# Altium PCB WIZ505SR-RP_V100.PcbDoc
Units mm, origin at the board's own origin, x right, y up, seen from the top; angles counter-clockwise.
Board outline 62 x 40 mm, 4 copper layers (Top Layer, Internal Plane 1, Internal Plane 2, Bottom Layer), stack 0.844 mm thick; 87 components, 75 nets, 318 pads, 242 vias.
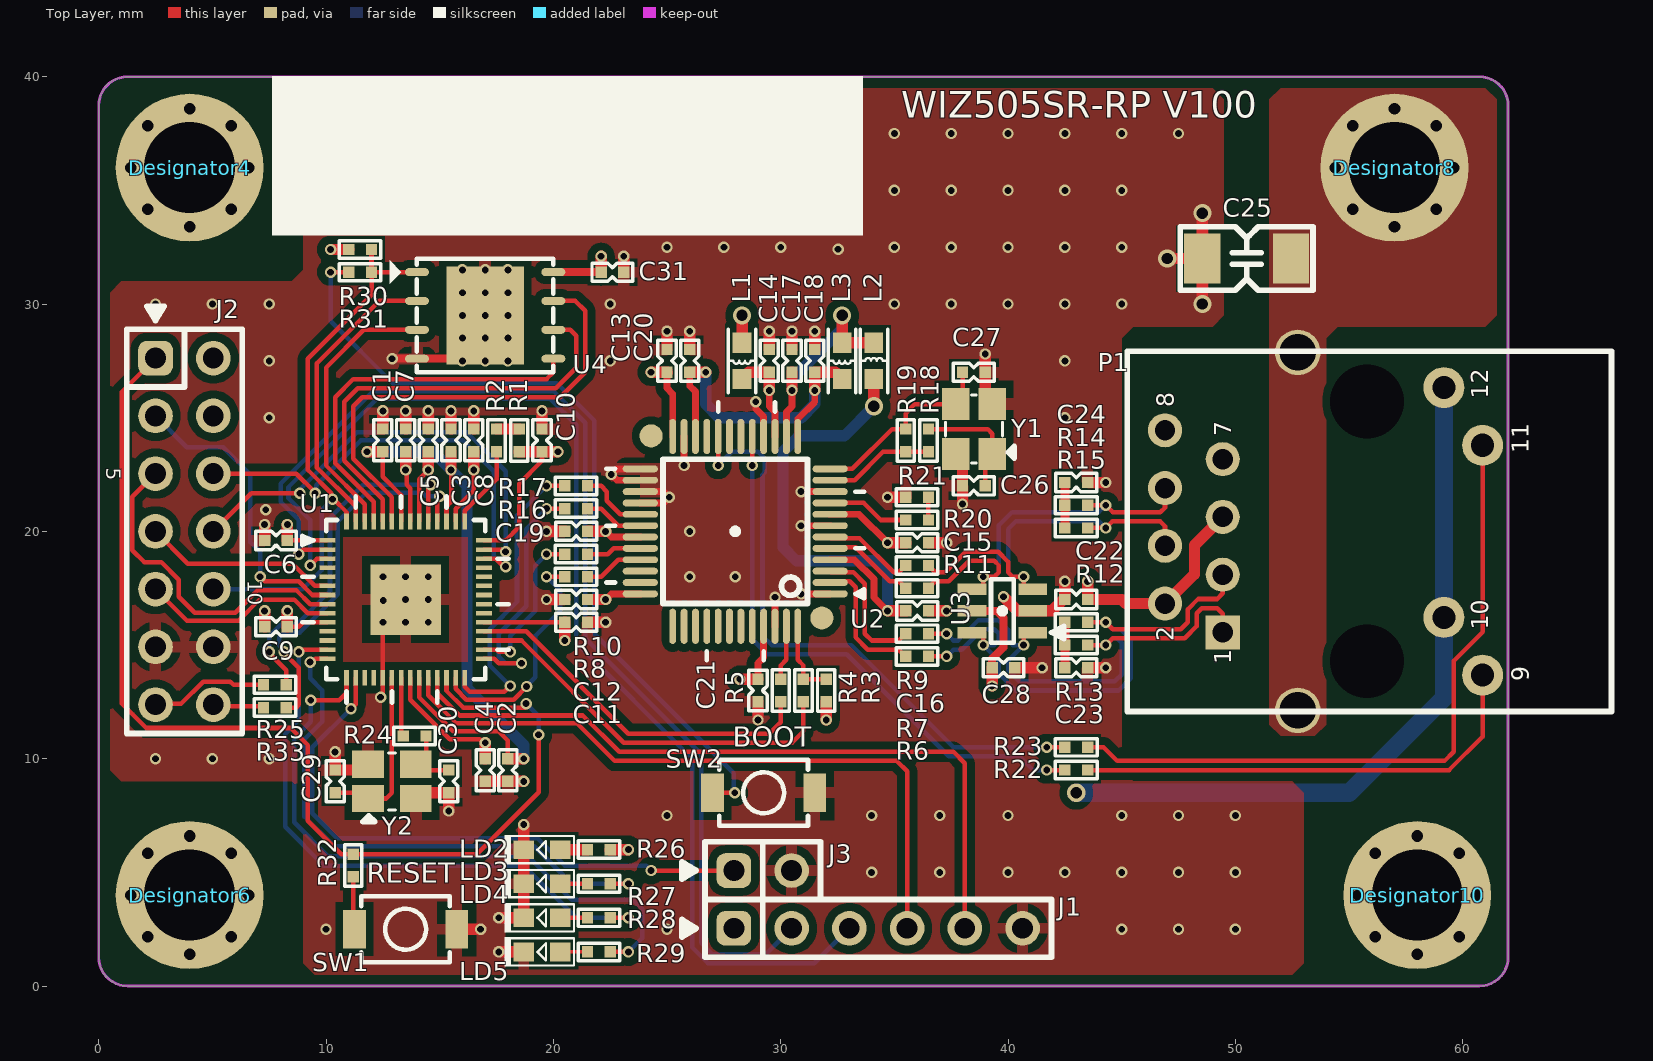
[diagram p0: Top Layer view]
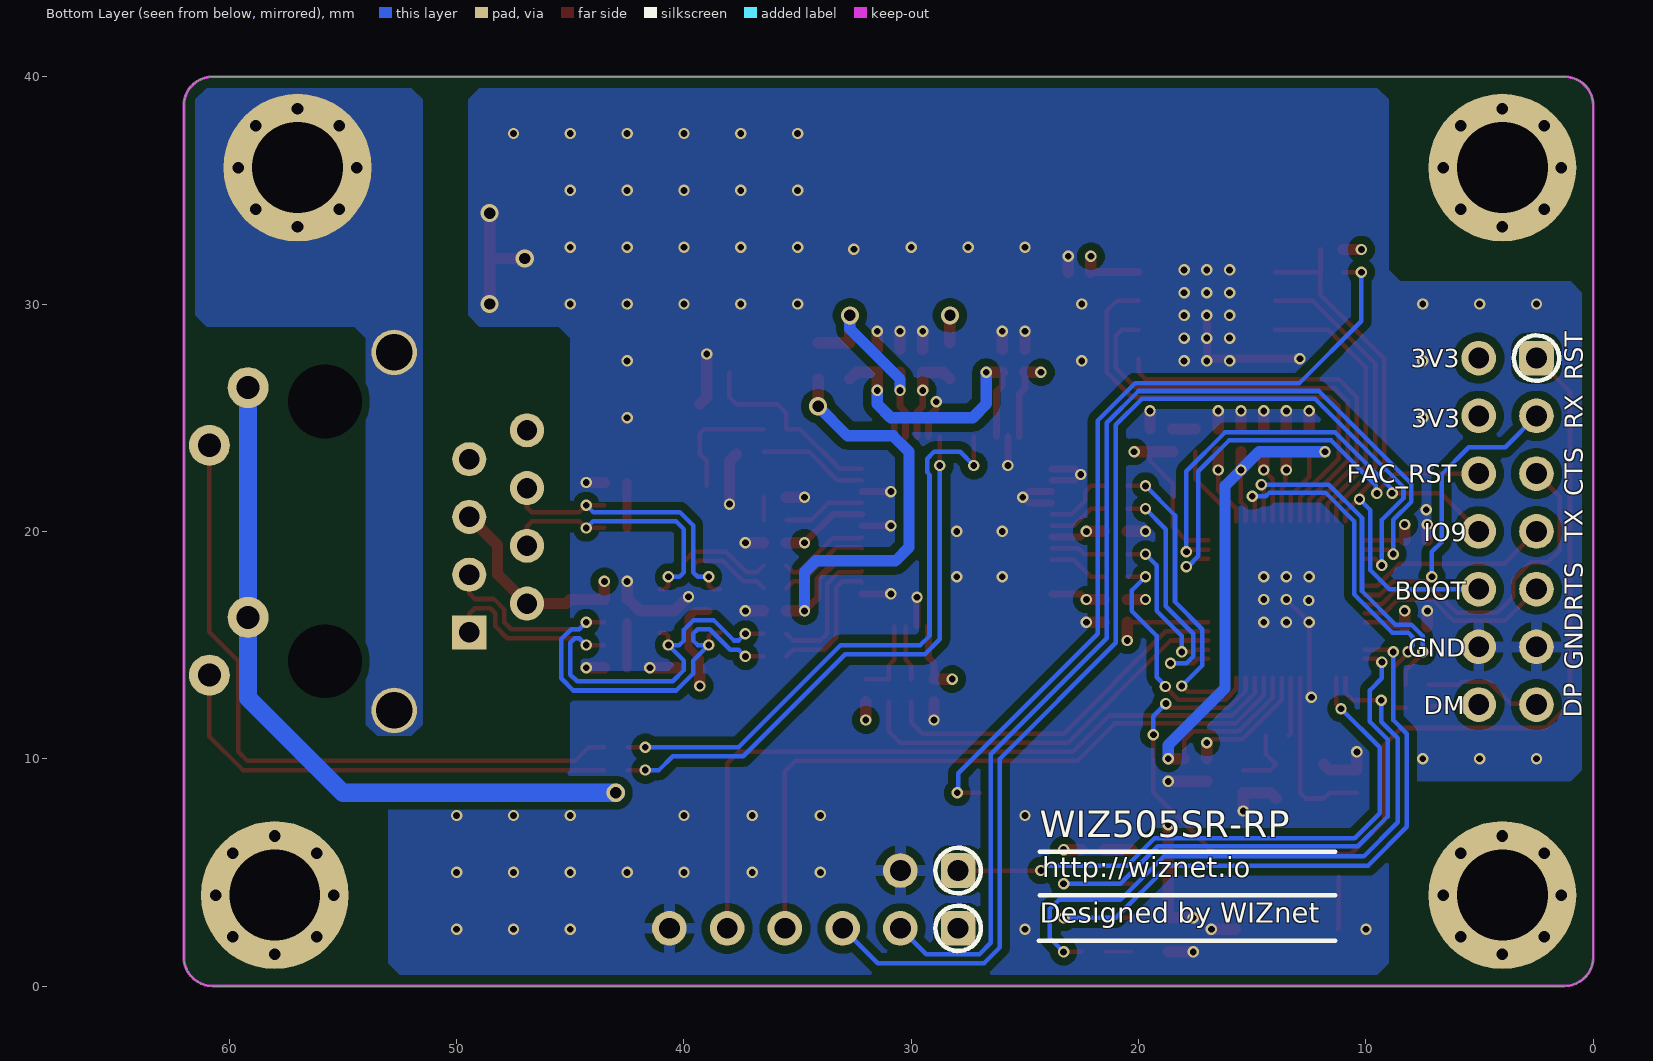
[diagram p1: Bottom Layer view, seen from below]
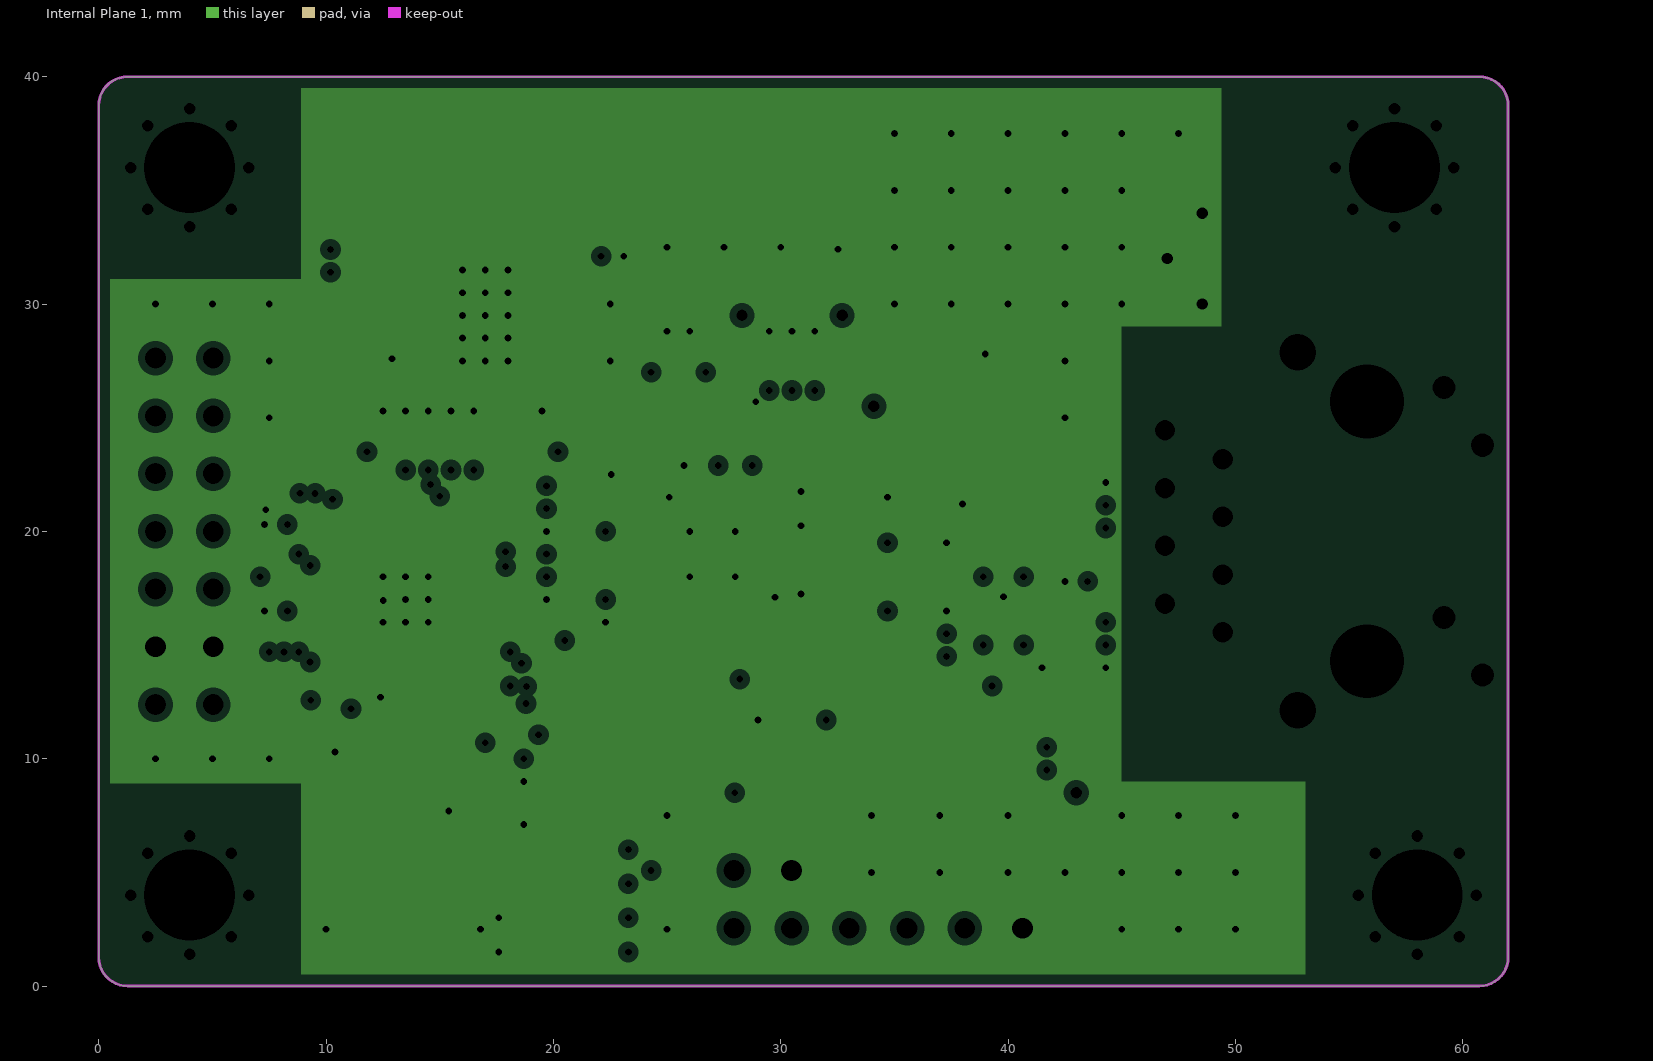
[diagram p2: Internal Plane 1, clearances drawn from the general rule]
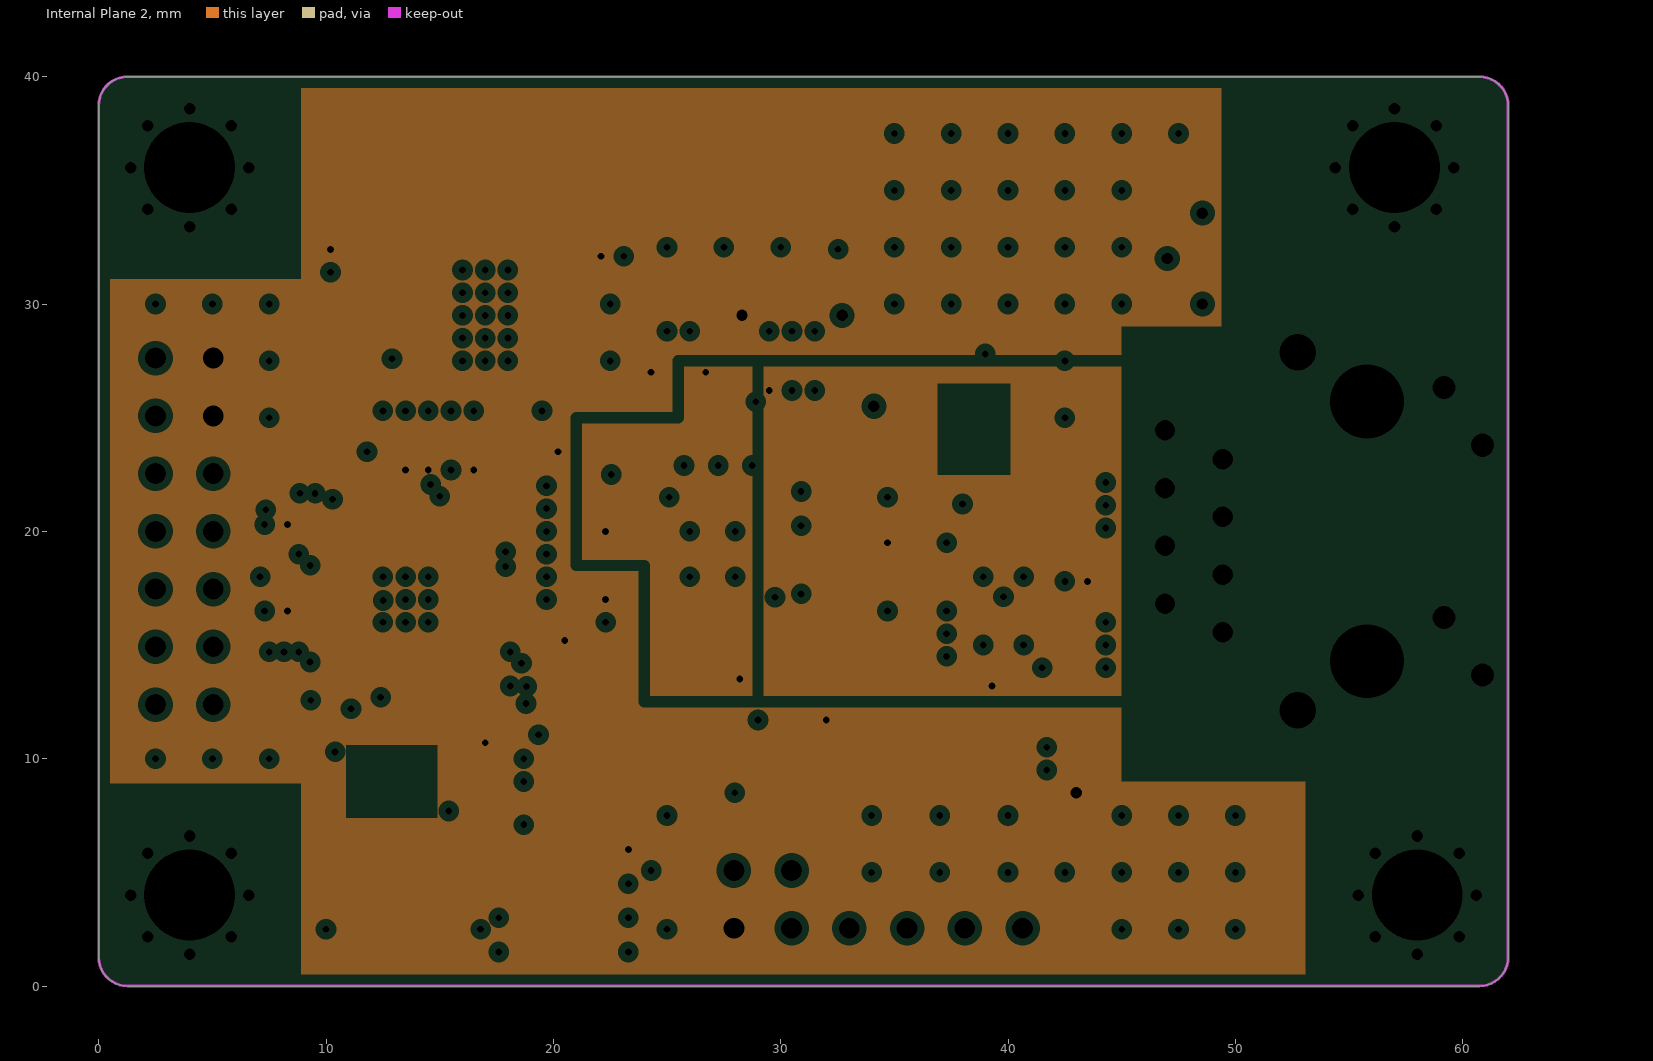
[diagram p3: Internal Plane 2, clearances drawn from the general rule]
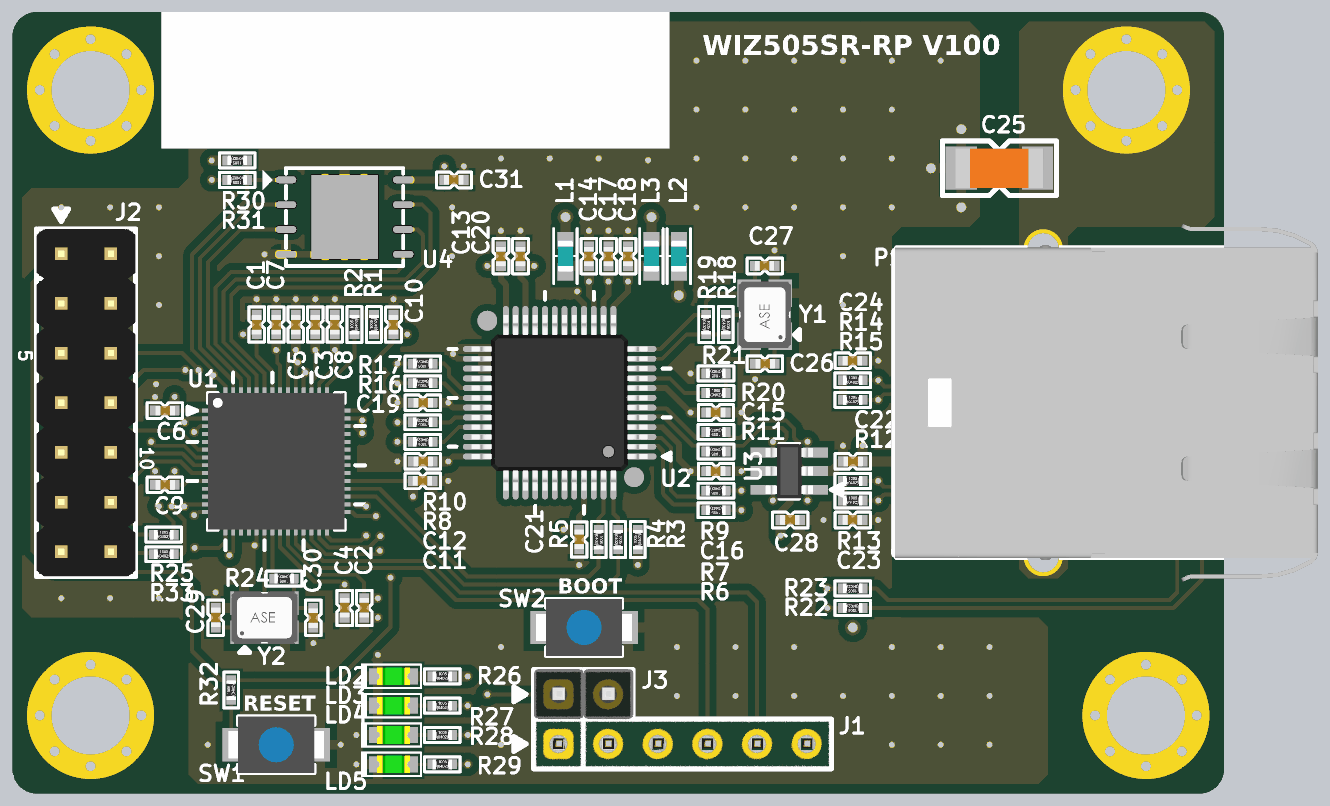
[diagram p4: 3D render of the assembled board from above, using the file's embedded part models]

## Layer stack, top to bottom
Top Solder: solder mask 0.0102, Solder Resist, Dk 3.5
Top Layer: signal copper 0.0356
Dielectric1: core 0.32, FR-4, Dk 4.8
Internal Plane 1: plane copper 0.0356, net GND
Dielectric 6: prepreg 0.127, Dk 4.2
Internal Plane 2: plane copper 0.036, net (Multiple Nets)
Dielectric5: core 0.254, FR-4, Dk 4.2
Bottom Layer: signal copper 0.0356
Bottom Solder: solder mask 0.0102, Solder Resist, Dk 3.5

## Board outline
0,1.27 0,38.73 cw(c1.27,38.73) 1.27,40 60.73,40 cw(c60.73,38.73) 62,38.73 62,1.27 cw(c60.73,1.27) 60.73,0 1.27,0 cw(c1.27,1.27)

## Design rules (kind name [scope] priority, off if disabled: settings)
Clearance [All] p1: gap=0.15 ignorepadtopadclearanceinfootprint=FALSE except(0: Arc-Hole Track-Hole SMDPad-Hole THPad-Hole Via-Hole Fill-Hole Region-Hole Text-Hole; 0.35: Arc-Poly Track-Poly SMDPad-Poly THPad-Poly Via-Poly Fill-Poly Poly-Poly Poly-Region Poly-Text Poly-Hole)
DiffPairsRouting [All] p1: maxlimit=0.2 minlimit=0.2 mostfreqgap=0.2 toplayer_minwidth=0.2 toplayer_maxwidth=0.2 toplayer_prefwidth=0.2 bottomlayer_minwidth=0.2 bottomlayer_maxwidth=0.2 bottomlayer_prefwidth=0.2 maxuncoupledlength=15.24
HoleSize [All] p1: absolutevalues=TRUE maxlimit=4.064 minlimit=0.025 maxpercent=80.000 minpercent=20.000
PlaneClearance [All] p1: clearance=0.305
PlaneConnect [All] p1: planeconnectstyle=Direct reliefexpansion=0.508 reliefentries=4 reliefconductorwidth=0.254 reliefairgap=0.254
PolygonConnect PolygonConnect_1 [InNet('CHGND')] p1: connectstyle=Direct reliefconductorwidth=0.254 reliefentries=4 polygonreliefangle="90 Angle" airgapwidth=0.254
PolygonConnect [All] p2: thpad.connectstyle=Relief thpad.reliefconductorwidth=0.5 thpad.reliefentries=4 thpad.polygonreliefangle="90 Angle" thpad.airgapwidth=0.35 smdpad.connectstyle=Relief smdpad.reliefconductorwidth=0.5 smdpad.reliefentries=4 smdpad.polygonreliefangle="90 Angle" smdpad.airgapwidth=0.35 via.connectstyle=Direct via.reliefconductorwidth=0.254 via.reliefentries=4 via.polygonreliefangle="90 Angle" via.airgapwidth=0.254
RoutingVias [All] p1: holewidth=0.3 width=0.5 viastyle="Through Hole" minholewidth=0.3 minwidth=0.5 maxholewidth=0.6 maxwidth=1
SolderMaskExpansion [All] p1: expansion=0 istentingtop=FALSE
Width [All] p1: maxlimit=2.54 minlimit=0.102 preferedwidth=0.152
26 further rules are at their usual default settings.

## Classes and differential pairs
component class 1.WIZ750JR_W7500: LD2
differential pair TX: +TX_P -TX_N
differential pair RX: +RX_P -RX_N

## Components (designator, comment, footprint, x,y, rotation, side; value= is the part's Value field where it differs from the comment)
C1 "1uF" CAP-0402 12.5,24 r270 top
C2 "0.1uF" CAP-0402 18,9.5 r90 top
C3 "0.1uF" CAP-0402 15.5,24 r270 top
C4 "1uF" CAP-0402 17,9.5 r90 top
C5 "0.1uF" CAP-0402 14.5,24 r270 top
C6 "0.1uF" CAP-0402 7.8,19.6 r0 top
C7 "0.1uF" CAP-0402 13.5,24 r270 top
C8 "0.1uF" CAP-0402 16.5,24 r270 top
C9 "0.1uF" CAP-0402 7.8,15.8 r0 top
C10 "0.1uF" CAP-0402 19.5,24 r270 top
C11 "0.1uF" CAP-0402 21,16 r180 top
C12 "0.1uF" CAP-0402 21,17 r0 top
C13 "0.1uF" CAP-0402 25,27.5 r270 top
C14 "0.1uF" CAP-0402 29.5,27.5 r270 top
C15 "0.1uF" CAP-0402 36,19.5 r180 top
C16 "0.1uF" CAP-0402 36,16.5 r180 top
C17 "1uF" CAP-0402 30.5,27.5 r270 top
C18 "0.1uF" CAP-0402 31.5,27.5 r270 top
C19 "0.1uF" CAP-0402 21,20 r0 top
C20 "0.1uF" CAP-0402 26,27.5 r270 top
C21 "0.1uF" CAP-0402 29,13 r90 top
C22 "0.1uF" CAP-0402 43,17 r0 top
C23 "0.1uF" CAP-0402 43,14 r180 top
C24 "0.1uF" CAP-0402 43,22.15 r180 top
C25 "1nF/2kV" CAP-1808 50.5,32 r0 top
C26 "18pF" CAP-0402 38.5,22 r0 top
C27 "18pF" CAP-0402 38.5,27 r180 top
C28 "0.1uF" CAP-0402 39.8,14 r180 top
C29 "15pF" CAP-0402 10.4,9 r90 top
C30 "15pF" CAP-0402 15.4,9 r270 top
C31 "0.1uF" CAP-0402 22.6,31.4 r180 top
Designator4 "Comment" HOLE-4/6.5 4,36 r0 top
Designator6 "Comment" HOLE-4/6.5 4,4 r0 top
Designator8 "Comment" HOLE-4/6.5 57,36 r0 top
Designator10 "Comment" HOLE-4/6.5 58,4 r0 top
J1 "2.54mm 1x6 Pin Header DIP" IDC-1X6 27.94,2.54 r0 top
J2 "2.54mm 2x7 Pin Header DIP" IDC-2X7 2.5,27.62 r270 top
J3 "2.54mm 1x2 Pin Header DIP" IDC-1X2 27.94,5.08 r0 top
L1 "HH-1M1608-121JT" IND-0603#1 28.3,27.5 r270 top
L2 "HH-1M1608-121JT" IND-0603#1 34.1,27.5 r90 top
L3 "HH-1M1608-121JT" IND-0603#2 32.7,27.5 r270 top
LD2 "Red" LED-0603-green 19.5,6 r180 top
LD3 "Green" LED-0603-green 19.5,4.5 r180 top
LD4 "Green" LED-0603-green 19.5,3 r180 top
LD5 "Green" LED-0603-green 19.5,1.5 r180 top
P1 "J1B1211CCD" RJ45-J1B1211CCD 63.595,20 r90 top locked
R1 "200R" RES-0402#1 18.5,24 r90 top
R2 "1R" RES-0402#1 17.5,24 r90 top
R3 "4.7K" RES-0402#1 32,13 r90 top
R4 "0R" RES-0402#1 31,13 r270 top
R5 "0R" RES-0402#1 30,13 r270 top
R6 "3.3R" RES-0402#1 36,14.5 r180 top
R7 "3.3R" RES-0402#1 36,15.5 r180 top
R8 "0R" RES-0402#1 21,18 r180 top
R9 "3.3R" RES-0402#1 36,17.5 r180 top
R10 "0R" RES-0402#1 21,19 r180 top
R11 "3.3R" RES-0402#1 36,18.5 r180 top
R12 "49.9R" RES-0402#1 43,16 r0 top
R13 "49.9R" RES-0402#1 43,15 r0 top
R14 "49.9R" RES-0402#1 43,21.15 r0 top
R15 "49.9R" RES-0402#1 43,20.15 r0 top
R16 "0R" RES-0402#1 21,21 r180 top
R17 "0R" RES-0402#1 21,22 r180 top
R18 "0R" RES-0402#1 36.5,24 r270 top
R19 "1M" RES-0402#1 35.5,24 r270 top
R20 "12K/1%" RES-0402#1 36,20.5 r0 top
R21 "300R" RES-0402#1 36,21.5 r180 top
R22 "470R" RES-0402#1 43,9.5 r180 top
R23 "470R" RES-0402#1 43,10.5 r180 top
R24 "1K" RES-0402#1 13.9,11 r180 top
R25 "0R" RES-0402#1 7.75,13.25 r0 top
R26 "470R" RES-0402#1 22,6 r0 top
R27 "470R" RES-0402#1 22,4.5 r0 top
R28 "470R" RES-0402#1 22,3 r0 top
R29 "470R" RES-0402#1 22,1.5 r0 top
R30 "NC" RES-0402#1 11.5,32.4 r180 top
R31 "1K" RES-0402#1 11.5,31.4 r180 top
R32 "1K" RES-0402#1 11.2,5.3 r90 top
R33 "0R" RES-0402#2 7.75,12.25 r0 top
SW1 "1185SA(2.0)" ST-1185S 13.5,2.5 r0 top
SW2 "1185SA(2.0)" ST-1185S 29.25,8.5 r0 top
U1 "RP2040" QFN56(0.4/7X7) 13.5,17 r0 top locked
U2 "W5100S" W5100S_LQFP48(0.5/9.0) 28,20 r180 top locked
U3 "TPD4S009DBKR" TPD4S009DBKR-SOT-23-6L 39.75,16.5 r180 top
U4 "W25Q16JVZPIM" WSON8(6X5_1.27) 17,29.5 r0 top
Y1 "25MHz" OSC-82J0626 38.5,24.5 r90 top
Y2 "12MHz" OSC-TZ1067B 12.9,9 r0 top

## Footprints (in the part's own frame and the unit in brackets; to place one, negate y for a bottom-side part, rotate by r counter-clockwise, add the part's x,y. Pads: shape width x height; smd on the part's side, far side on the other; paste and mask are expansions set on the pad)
CAP-0402 [mm] "Ceramic CAP 0402(1005)"
  rect 0.5x0.5 smd: 1(-0.5,0) 2(0.5,0)
  silkscreen extent -0.9,-0.4 0.9,0.4, body extent -0.48,-0.25 0.52,0.25, height 0.6
CAP-1808 [mm] "Ceramic CAP 1808(4520)"
  rect 1.6x2.2 smd: 1(-1.95,0) 2(1.95,0)
  silkscreen extent -2.92,-1.4 2.92,1.4, body extent -2.25,-1.02 2.25,1.01, height 2
HOLE-4/6.5 [mm]
  round 6.5 hole 4: 1(0,0)
IDC-1X2 [mil]
  rrect50% 60x60 hole 36: 1(0,0)
  round 60 hole 36: 2(100,0)
  silkscreen extent -90,-50 150,50, body extent -49,-49 151,51, height 336
IDC-1X6 [mil] "6-Way 2.54 mm Male Header"
  rrect50% 60x60 hole 36: 1(0,0)
  round 60 hole 36: 2(100,0) 3(200,0) 4(300,0) 5(400,0) 6(500,0)
  silkscreen extent -90,-50 550,50, body extent -49,-49 551,51, height 336
IDC-2X7 [mil]
  rrect50% 60x60 hole 36: 1(0,0)
  round 60 hole 36: 2(0,100) 3(100,0) 4(100,100) 5(200,0) 6(200,100) 7(300,0) 8(300,100) 9(400,0) 10(400,100) 11(500,0) 12(500,100) 13(600,0) 14(600,100)
  silkscreen extent -90,-50 650,150, body extent -50,-50 650,150, height 335
IND-0603#1 [mm] "Inductor 0603(1608)"
  rect 0.89x0.82 smd: 1(-0.8,0) 2(0.8,0)
  Top Layer pour cut-out: -0.254,0.508 -0.254,-0.508 0.254,-0.508 0.254,0.508
  silkscreen extent -1.4,-0.6 1.4,0.6, body extent -0.8,-0.4 0.8,0.4, height 0.95
IND-0603#2 [mm] "Inductor 0603(1608)"
  rect 0.89x0.82 smd: 1(-0.8,0) 2(0.8,0)
  silkscreen extent -1.4,-0.6 1.4,0.6, body extent -0.8,-0.4 0.8,0.4, height 0.95
LED-0603-green [mm] "LED-0603-GREEN"
  rect 0.89x0.82 smd: 1(-0.8,0) 2(0.8,0)
  silkscreen extent -1.41,-0.65 1.65,0.65, body extent -0.85,-0.45 0.85,0.45, height 0.9
OSC-82J0626 [mm]
  rect 1.4x1.2 smd: 1(-1.1,-0.8) 2(1.1,-0.8) 3(1.1,0.8) 4(-1.1,0.8)
  silkscreen extent -1.5,-1.78 1.5,1.25, body extent -1.7,-1.35 1.7,1.35, height 1.06
OSC-TZ1067B [mm]
  rect 1.4x1.2 smd: 1(-1.05,-0.75) 2(1.05,-0.75) 3(1.05,0.75) 4(-1.05,0.75)
  silkscreen extent -1.27,-1.78 0.15,1.25, body extent -1.7,-1.35 1.7,1.35, height 1.06
QFN56(0.4/7X7) [mm]
  rect 0.7x0.2 smd: 1(-3.44,2.6) 2(-3.44,2.2) 3(-3.44,1.8) 4(-3.44,1.4) 5(-3.44,1) 6(-3.44,0.6) 7(-3.44,0.2) 8(-3.44,-0.2) 9(-3.44,-0.6) 10(-3.44,-1) 11(-3.44,-1.4) 12(-3.44,-1.8) 13(-3.44,-2.2) 14(-3.44,-2.6) 29(3.44,-2.6) 30(3.44,-2.2) 31(3.44,-1.8) 32(3.44,-1.4) 33(3.44,-1) 34(3.44,-0.6) 35(3.44,-0.2) 36(3.44,0.2) 37(3.44,0.6) 38(3.44,1) 39(3.44,1.4) 40(3.44,1.8) 41(3.44,2.2) 42(3.44,2.6)
  rect 0.2x0.7 smd: 15(-2.6,-3.44) 16(-2.2,-3.44) 17(-1.8,-3.44) 18(-1.4,-3.44) 19(-1,-3.44) 20(-0.6,-3.44) 21(-0.2,-3.44) 22(0.2,-3.44) 23(0.6,-3.44) 24(1,-3.44) 25(1.4,-3.44) 26(1.8,-3.44) 27(2.2,-3.44) 28(2.6,-3.44) 43(2.6,3.44) 44(2.2,3.44) 45(1.8,3.44) 46(1.4,3.44) 47(1,3.44) 48(0.6,3.44) 49(0.2,3.44) 50(-0.2,3.44) 51(-0.6,3.44) 52(-1,3.44) 53(-1.4,3.44) 54(-1.8,3.44) 55(-2.2,3.44) 56(-2.6,3.44)
  rect 3.1x3.1 smd: 57(0,0)
  silkscreen extent -4.54,-4.54 4.54,4.54, body extent -3.5,-3.5 3.5,3.5, height 0.8
RES-0402#1 [mm]
  rect 0.5x0.5 smd: 1(-0.5,0) 2(0.5,0)
  silkscreen extent -0.91,-0.38 0.91,0.38, body extent -0.5,-0.25 0.5,0.25, height 0.35
RES-0402#2 [mm]
  rect 0.5x0.5 smd: 1(-0.5,-0.004) 2(0.5,-0.004)
  silkscreen extent -0.91,-0.38 0.91,0.38, body extent -0.5,-0.25 0.5,0.25, height 0.35
RJ45-J1B1211CCD [mm]
  rect 1.5x1.5 hole 0.9: 1(-4.445,14.15)
  round 1.5 hole 0.9: 2(-3.175,16.69) 3(-1.905,14.15) 4(-0.635,16.69) 5(0.635,14.15) 6(1.905,16.69) 7(3.175,14.15) 8(4.445,16.69)
  round 1.8 hole 1.02: 9(-6.325,2.72) 10(-3.785,4.42) 11(3.785,2.72) 12(6.325,4.42)
  round 2 hole 1.6: S1(-7.875,10.85) S2(7.875,10.85)
  round 1.8 hole 3.25: ""(-5.715,7.8) ""(5.715,7.8)
  silkscreen extent -7.93,-2.95 7.93,18.35, body extent -9.16,-3.2 9.16,18.64, height 15.09
ST-1185S [mm]
  rect 1x1.7 smd: 1(-2.25,0) 2(2.25,0)
  silkscreen extent -1.95,-1.45 1.95,1.45, body extent -2.45,-1.45 2.45,1.45, height 2
TPD4S009DBKR-SOT-23-6L [mm] "4-Channel ESD Solution for High-Speed Differential Interface"
  rect 1.27x0.508 smd: 1(-1.34,0.95) 2(-1.34,0) 3(-1.34,-0.95) 4(1.34,-0.95) 5(1.34,0) 6(1.34,0.95)
  silkscreen extent -2.72,-1.4 0.5,1.4, body extent -1.21,-1.4 1.21,1.4, height 1.09
W5100S_LQFP48(0.5/9.0) [mm]
  round 1.016 smd: 0(-3.81,3.81) 0(3.7,-4.2)
  oval 1.55x0.3 smd: 1(-4.175,2.75) 2(-4.175,2.25) 3(-4.175,1.75) 4(-4.175,1.25) 5(-4.175,0.75) 6(-4.175,0.25) 7(-4.175,-0.25) 8(-4.175,-0.75) 9(-4.175,-1.25) 10(-4.175,-1.75) 11(-4.175,-2.25) 12(-4.175,-2.75) 25(4.175,-2.75) 26(4.175,-2.25) 27(4.175,-1.75) 28(4.175,-1.25) 29(4.175,-0.75) 30(4.175,-0.25) 31(4.175,0.25) 32(4.175,0.75) 33(4.175,1.25) 34(4.175,1.75) 35(4.175,2.25) 36(4.175,2.75)
  oval 0.3x1.55 smd: 13(-2.75,-4.175) 14(-2.25,-4.175) 15(-1.75,-4.175) 16(-1.25,-4.175) 17(-0.75,-4.175) 18(-0.25,-4.175) 19(0.25,-4.175) 20(0.75,-4.175) 21(1.25,-4.175) 22(1.75,-4.175) 23(2.25,-4.175) 24(2.75,-4.175) 37(2.75,4.175) 38(2.25,4.175) 39(1.75,4.175) 40(1.25,4.175) 41(0.75,4.175) 42(0.25,4.175) 43(-0.25,4.175) 44(-0.75,4.175) 45(-1.25,4.175) 46(-1.75,4.175) 47(-2.25,4.175) 48(-2.75,4.175)
  silkscreen extent -5.67,-5.67 5.68,5.68, body extent -4.5,-4.5 4.5,4.5, height 1.5
WSON8(6X5_1.27) [mm]
  oval 1.05x0.35 smd mask+0.05: 1(-3,1.905) 2(-3,0.635) 3(-3,-0.635) 4(-3,-1.905) 5(3,-1.905) 6(3,-0.635) 7(3,0.635) 8(3,1.905)
  rect 3.4x4.3 smd mask+0.05: 9(0,0)
  silkscreen extent -4.2,-2.5 3,2.5, body extent -3,-2.5 3,2.5, height 0.8

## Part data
C1 C2 C3 C4 C5 C6 C7 C8 C9 C10 C11 C12 C13 C14 C15 C16 C17 C18 C19 C20 C21 C22 C23 C24 C26 C27 C28 C29 C30 C31: library part CAP-0402, "Ceramic CAP 0402(1005)"
C25: library part CAP-1808, "Ceramic CAP 1808(4520)"
L1 L2 L3: library part IND-0603, "Inductor 0603(1608)"
LD2 LD3 LD4 LD5: library part LED-0603, "LED-0603"
R1 R2 R3 R4 R5 R6 R7 R8 R9 R10 R11 R12 R13 R14 R15 R16 R17 R18 R19 R20 R21 R22 R23 R24 R25 R26 R27 R28 R29 R30 R31 R32 R33: library part RES-0402, "RES-0402"
SW1 SW2: library part ITS-1107(SMD), "TACT Switch (SMD)"
U1: "Raspverry Pi, Dual ARM Cortex-M0+ @ 133MHz"
U2: "WIZnet Hardwired TCP/IP Chip"
U3: "4-Channel ESD Solution for High-Speed Differential Interface"
U4: "3V 16M-BIT / SERIAL FLASH MEMORY WITH / DUAL/QUAD SPI, QPI & DTR"
Y1: library part OSC-82J0626-25MHz, "X-tal 25MHz,3.2x2.5 SMD, CL=18pF"
Y2: library part OSC-TZ1067B-12MHz, "X-tal 12MHz,3.2x2.5 SMD, CL=20pF"

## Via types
v1: diameter 0.5, hole 0.3, Top Layer to Bottom Layer, tented both sides, 203 vias
v2: diameter 0.762, hole 0.508, Top Layer to Bottom Layer, 32 vias
v3: diameter 0.8, hole 0.5, Top Layer to Bottom Layer, tented both sides, 7 vias

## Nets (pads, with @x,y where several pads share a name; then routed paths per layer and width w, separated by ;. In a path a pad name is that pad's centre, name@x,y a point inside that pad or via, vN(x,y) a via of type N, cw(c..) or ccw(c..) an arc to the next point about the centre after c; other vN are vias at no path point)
1V1: C1.2 C2.2 C3.2 U1.23 U1.45 U1.50 | length 32.3
  Top Layer w0.2: C1.2 12.5,22.4 13.3,21.6 U1.50 ; U1.23 14.1,12.695 15.595,11.2 17.6,11.2 18,10.8 C2.2 ; U1.45 15.3,21.09 15.5,21.29 v1(15.5,22.7)
  Top Layer w0.5: v1(11.8,23.5) C1.2 ; v1(15.5,22.7) C3.2 ; C2.2 v1(18.7,10)
  Bottom Layer w0.5: v1(11.8,23.5) 14.7,23.5 16.2,22 16.2,13.1 18.7,10.6 v1(18.7,10)
1V2A: C16.2 L2.1 U2.4 | length 21.7
  Top Layer w0.3: U2.4 33.25,18.75 34.1,17.9 34.1,17.1 v1(34.7,16.5)
  Top Layer w0.5: v3(34.1,25.5) L2.1 ; v1(34.7,16.5) C16.2
  Bottom Layer w0.5: v3(34.1,25.5) 32.8,24.2 30.8,24.2 30.1,23.5 30.1,19.3 30.7,18.7 34.2,18.7 34.7,18.2 v1(34.7,16.5)
1V2D: C18.2 C19.2 C20.2 C21.2 L3.2 U2.13 U2.22 U2.31 U2.45 | length 21
  Top Layer w0.3: v1(22.3,20) 22.55,19.75 U2.31 ; C20.2 26,26.4 26.25,26.15 U2.22 ; C21.2 29,14.2 29.25,14.45 U2.45 ; U2.13 30.75,24.95 31.5,25.7 v1(31.5,26.2)
  Top Layer w0.5: C19.2 v1(22.3,20) ; C20.2 v1(26.7,27) ; v1(28.2,13.5) C21.2 ; v1(31.5,26.2) C18.2 32.4,27 L3.2
  Bottom Layer w0.5: v1(26.7,27) 26.7,25.6 27.3,25 30.9,25 31.5,25.6 v1(31.5,26.2)
1V2O: C17.2 L2.2 L3.1 U2.14 | length 9.7
  Top Layer w0.3: U2.14 30.25,25.25 30.5,25.5 v1(30.5,26.2)
  Top Layer w0.5: v1(30.5,26.2) C17.2 ; v3(32.7,29.5) L3.1 L2.2
  Bottom Layer w0.5: v1(30.5,26.2) 30.5,26.7 32.7,28.9 v3(32.7,29.5)
3V3: C4.2 C5.2 C6.2 C7.2 C8.2 C9.2 C10.2 C11.2 C12.2 C13.2 C31.2 J1.1 J2.2 J2.4 L1.1 P1.10 P1.12 R1.1 R3.1 R26.2 R30.2 U1.1 U1.10 U1.22 U1.33 U1.42 U1.44 U1.48 U1.49 U2.24 U2.36 U4.8 | length 76.1
  Top Layer w0.2: C9.2 8.8,15.8 9,16 U1.10 ; C6.2 U1.1 ; v1(13.5,22.7) 13.55,22.65 13.55,22.05 13.7,21.9 U1.49 ; U1.22 13.7,12.6 15.45,10.85 16.769,10.85 16.919,10.7 v1(17,10.7) ; U1.48 14.1,22.3 v1(14.5,22.7) ; U1.44 15.7,20.995 16.5,21.795 v1(16.5,22.7) ; U1.33 C11.2 ; U1.42 17.9,19.6 18.5,20.2 18.5,22.1 19.5,23.1 C10.2
  Top Layer w0.3: v1(22.3,17) 22.55,17.25 U2.36 ; C13.2 25,26.3 25.25,26.05 U2.24
  Top Layer w0.35: U4.8 22.095,31.405 C31.2
  Top Layer w0.5: C9.2 v1(8.3,16.5) ; C6.2 v1(8.3,20.3) ; v1(10.2,32.4) R30.2 ; v1(13.5,22.7) C7.2 ; v1(14.5,22.7) C5.2 ; v1(16.5,22.7) C8.2 ; C4.2 v1(17,10.7) ; R1.1 C10.2 v1(20.2,23.5) ; v1(20.5,15.2) C11.2 ; C12.2 v1(22.3,17) ; C31.2 v1(22.1,32.1) ; R26.2 v1(23.3,6) ; v1(32,11.7) R3.1
  Top Layer w0.508: v1(24.3,27) C13.2 ; L1.1 v3(28.3,29.5)
  Bottom Layer w0.8: v3(43,8.5) 55,8.5 59.175,12.675 P1.10 P1.12
3V3A: C14.2 C15.2 C22.2 C28.2 L1.2 P1.2 P1.5 U2.8 U2.15 U3.5 | length 21.5
  Top Layer w0.3: v1(29.5,26.2) 29.5,25.5 29.75,25.25 U2.15 ; U2.8 33.45,20.75 v1(34.7,19.5)
  Top Layer w0.35: U3.5@38.912,16.5 39.5,16.5 39.8,16.2 39.8,14.9 39.3,14.4 C28.2
  Top Layer w0.5: L1.2 28.6,27 C14.2 v1(29.5,26.2) ; v1(34.7,19.5) C15.2 ; v1(39.3,13.2) C28.2 ; v1(43.5,17.8) C22.2 45,17 45.175,16.825 P1.2 48.2,18.12 48.2,19.39 P1.5
ACTn: R23.2 U2.20 | length 26.9
  Top Layer w0.2: v1(27.25,22.9) U2.20 ; v1(41.7,10.5) R23.2
  Bottom Layer w0.2: v1(27.25,22.9) 27.85,23.5 29,23.5 29.3,23.2 29.3,22.6 29.2,22.5 29.2,15.4 29.6,15 33.1,15 37.6,10.5 v1(41.7,10.5)
ADC_VREF: R1.2 R2.2 | length 1
  Top Layer w0.5: R2.2 R1.2
BLINK: R29.2 U1.15 | length 27.9
  Top Layer w0.2: v1(9.325,12.575) 10.575,12.575 10.9,12.9 U1.15 ; R29.2 v1(23.3,1.5)
  Bottom Layer w0.2: v1(9.325,12.575) 9.325,11.625 8.6,10.9 8.6,7.2 10.1,5.7 18.9,5.7 20.8,3.8 23.5,3.8 23.9,3.4 23.9,2.1 v1(23.3,1.5)
BOOTSEL: J2.10 R30.1 R31.1 U1.56 U4.1 | length 24.3
  Top Layer w0.2: U1.56 10.9,20.85 10.34,21.41 v1(10.283,21.41) 10.226,21.467 10.226,21.68 9.205,22.7 9.2,22.7 9.2,27.6 12.005,30.405 R31.1@12.005,31.405 ; R30.1 R31.1 R31.1@12.005,31.405 ; U4.1 R31.1@12.005,31.405
  Bottom Layer w0.2: J2.10 8.967,17.46 9.804,18.296 9.804,20.931 v1(10.283,21.41)
CHGND: C25.2 Designator8.1 P1.S1 P1.S2
  other v2: 57,33.4 55.162,34.162 58.838,34.162 54.4,36 59.6,36 55.162,37.838 58.838,37.838 57,38.6
FACT_RST: J2.6 U1.40 | length 20
  Top Layer w0.2: J2.6 8.692,22.54 9.52,21.712 v1(9.52,21.673) ; U1.40 17.472,18.8 17.822,18.45 v1(17.9,18.45)
  Bottom Layer w0.2: v1(9.52,21.673) 9.568,21.72 9.568,22.034 11.533,24 16.025,24 17.375,22.65 17.375,18.918 17.843,18.45 v1(17.9,18.45)
GND: C1.1 C2.1 C3.1 C4.1 C5.1 C6.1 C7.1 C8.1 C9.1 C10.1 C11.1 C12.1 C13.1 C14.1 C15.1 C16.1 C17.1 C18.1 C19.1 C20.1 C21.1 C22.1 C23.1 C24.1 C25.1 C26.1 C27.1 C28.1 C29.2 C30.2 C31.1 J1.6 J2.11 J2.12 J3.2 LD2.2 LD3.2 LD4.2 LD5.2 R21.2 SW1.2 SW2.2 U1.19 U1.57 U2.1 U2.7 U2.10 U2.16 U2.23 U2.25 U2.26 U2.27 U2.28 U2.46 U3.2 U4.4 U4.9 Y1.2 Y1.4 Y2.2 Y2.4 | length 71.5
  Top Layer w0.2: v1(12.4,12.7) 12.5,12.8 U1.19 v1(12.5,16) v1(13.5,17)
  Top Layer w0.3: U2.28 24.85,21.25 v1(25.1,21.5) 24.85,21.75 U2.27 ; U2.26 22.8,22.25 v1(22.55,22.5) 22.8,22.75 U2.25 ; v1(25.75,22.9) U2.23 ; v1(28.9,25.7) 28.9,25.4 29.25,25.05 U2.16 ; U2.46 v1(29.75,17.1) ; v1(30.9,17.25) U2.1 ; v1(30.9,20.25) U2.7 ; v1(30.9,21.75) U2.10
  Top Layer w0.35: v1(12.905,27.595) U4.4 17,27.595 v1(17,29.5)
  Top Layer w0.5: C9.1 v1(7.3,16.5) ; C6.1 v1(7.3,20.3) ; v1(10.4,10.3) C29.2 11.6,9.5 Y2.4 ; C1.1 v1(12.5,25.3) ; C7.1 v1(13.5,25.3) ; Y2.2 14.2,8.5 C30.2 v1(15.4,7.7) ; C5.1 v1(14.5,25.3) ; C3.1 v1(15.5,25.3) ; SW1.2 v1(16.8,2.5) ; C8.1 v1(16.5,25.3) ; C4.1 C2.1 v1(18.7,9) ; v1(17.6,1.5) LD5.2 ; v1(17.6,3) LD4.2 LD3.2 LD2.2 v1(18.7,7.1) ; C10.1 v1(19.5,25.3) ; v1(19.7,17) C12.1 ; v1(19.7,20) C19.1 ; C11.1 v1(22.3,16) ; C31.1 v1(23.1,32.1) ; C13.1 v1(25,28.8) ; C20.1 v1(26,28.8) ; v1(29,11.7) C21.1 ; C14.1 v1(29.5,28.8) ; C17.1 v1(30.5,28.8) ; C18.1 v1(31.5,28.8) ; v1(34.7,21.5) R21.2 ; C16.1 v1(37.3,16.5) ; C15.1 v1(37.3,19.5) ; Y1.4 38,23.1 C26.1 v1(38,21.2) ; v1(39,27.8) C27.1 39,25.9 Y1.2 ; v1(39.8,17.125) 40.425,16.5 U3.2 41.094,16.504 41.938,16.504 42.434,17 C22.1 v1(42.5,17.8) ; C28.1 v1(41.5,14) ; C23.1 v1(44.3,14) ; C24.1 v1(44.3,22.15) ; v3(47,32) C25.1 ; v3(48.55,30) C25.1 ; v3(48.55,34) C25.1
  other v1: 10,2.5 25,2.5 45,2.5 47.5,2.5 50,2.5 34,5 37,5 40,5 42.5,5 45,5 47.5,5 50,5 25,7.5 34,7.5 37,7.5 40,7.5 45,7.5 47.5,7.5 50,7.5 2.5,10 5,10 7.5,10 13.5,16 14.5,16 12.519,16.96 14.5,17 12.5,18 13.5,18 14.5,18 26,18 28,18 26,20 28,20 7.35,20.95 7.5,25 42.5,25 7.5,27.5 16,27.5 17,27.5 18,27.5 22.5,27.5 42.5,27.5 16,28.5 17,28.5 18,28.5 16,29.5 18,29.5 2.5,30 5,30 7.5,30 22.5,30 35,30 37.5,30 40,30 42.5,30 45,30 16,30.5 17,30.5 18,30.5 16,31.5 17,31.5 18,31.5 32.526,32.407 25,32.5 27.5,32.5 30,32.5 35,32.5 37.5,32.5 40,32.5 42.5,32.5 45,32.5 35,35 37.5,35 40,35 42.5,35 45,35 35,37.5 37.5,37.5 40,37.5 42.5,37.5 45,37.5 47.5,37.5
HW_TRIG: J2.8 U1.41 | length 20
  Top Layer w0.2: J2.8 6.715,21.675 v1(8.85,21.675) ; U1.41 17.719,19.2 17.819,19.1 v1(17.9,19.1)
  Bottom Layer w0.2: v1(8.85,21.675) 8.907,21.732 8.907,21.907 11.35,24.35 16.2,24.35 17.9,22.65 v1(17.9,19.1)
INTn: R5.2 U1.32 | length 16
  Top Layer w0.2: U1.32 18.8,15.6 23.3,11.1 29.5,11.1 30,11.6 R5.2
LINK_STATUS: R28.2 U1.13 | length 26.8
  Top Layer w0.2: v1(8.8,14.7) 8.9,14.8 U1.13 ; R28.2 v1(23.3,3)
  Bottom Layer w0.2: v1(8.8,14.7) 8.8,11.7 8.2,11.1 8.2,7 9.9,5.3 18.7,5.3 21,3 v1(23.3,3)
LINKn: R22.2 U2.17 | length 25.1
  Top Layer w0.2: v1(28.75,22.9) U2.17 ; v1(41.7,9.5) R22.2
  Bottom Layer w0.2: v1(28.75,22.9) 28.75,15.25 29.4,14.6 32.9,14.6 37.4,10.1 40.5,10.1 41.1,9.5 v1(41.7,9.5)
NetC23_2: C23.2 R12.1 R13.1 | length 2
  Top Layer w0.4: C23.2 R13.1 R12.1
NetC24_2: C24.2 R14.1 R15.1 | length 2
  Top Layer w0.4: R15.1 R14.1 C24.2
NetC26_2: C26.2 R18.1 Y1.1 | length 5.3
  Top Layer w0.2: R18.1 39.1,24.5 39.3,24.3 Y1.1 39,23.1 C26.2
NetC27_2: C27.2 R19.1 U2.12 Y1.3 | length 8.6
  Top Layer w0.2: U2.12 33.15,22.75 34.9,24.5 R19.1 35.5,25.2 35.9,25.6 Y1.3 38,25.9 C27.2
NetC30_1: C30.1 R24.1 Y2.3 | length 3
  Top Layer w0.2: R24.1 14.4,10.2 Y2.3 14.2,9.5 C30.1
NetLD2_1: LD2.1 R26.1 | length 1.2
  Top Layer w0.5: LD2.1 R26.1
NetLD3_1: LD3.1 R27.1 | length 1.2
  Top Layer w0.2: LD3.1 R27.1
NetLD4_1: LD4.1 R28.1 | length 1.2
  Top Layer w0.2: LD4.1 R28.1
NetLD5_1: LD5.1 R29.1 | length 1.2
  Top Layer w0.152: LD5.1 R29.1
NetP1_9: P1.9 R22.1 | length 20.7
  Top Layer w0.2: R22.1 59.4,9.5 60.875,10.975 P1.9
NetP1_11: P1.11 R23.1 | length 30.5
  Top Layer w0.2: R23.1 44.2,10.5 44.8,9.9 59.2,9.9 59.6,10.3 59.6,14.3 60.875,15.575 P1.11
NetR2_1: R2.1 U1.43 | length 3.6
  Top Layer w0.2: U1.43 16.1,20.9 17.5,22.3 R2.1
NetR3_2: R3.2 R4.1 U2.48 | length 3.4
  Top Layer w0.2: U2.48 30.75,14.35 31,14.1 R4.1 R3.2
NetR5_1: R5.1 U2.47 | length 2.4
  Top Layer w0.2: R5.1 30,14.1 30.25,14.35 U2.47
NetR6_2: R6.2 U2.2 | length 6
  Top Layer w0.2: U2.2 32.225,17.8 33.034,17.8 33.3,17.534 33.3,15.334 33.834,14.8 35.2,14.8 R6.2
NetR7_2: R7.2 U2.3 | length 6
  Top Layer w0.2: U2.3 32.225,18.2 33.2,18.2 33.7,17.7 33.7,15.5 34,15.2 35.2,15.2 R7.2
NetR8_1: R8.1 U2.33 | length 2.6
  Top Layer w0.2: R8.1 22.1,18 22.85,18.75 U2.33
NetR9_2: R9.2 U2.5 | length 4.1
  Top Layer w0.2: U2.5 32.225,19.3 33.3,19.3 34.8,17.8 35.2,17.8 R9.2
NetR10_1: R10.1 U2.32 | length 2.4
  Top Layer w0.2: R10.1 22.4,19 22.65,19.25 U2.32
NetR11_2: R11.2 U2.6 | length 4.1
  Top Layer w0.2: U2.6 32.225,19.7 33.466,19.7 34.966,18.2 35.2,18.2 R11.2
NetR16_1: R16.1 U2.30 | length 2.6
  Top Layer w0.2: R16.1 22.1,21 22.85,20.25 U2.30
NetR17_1: R17.1 U2.29 | length 3.1
  Top Layer w0.2: R17.1 22.1,22 22.35,21.75 22.35,21.35 22.95,20.75 U2.29
NetR18_2: R18.2 R19.2 U2.11 | length 4.8
  Top Layer w0.2: U2.11 33.25,22.25 34.5,23.5 R19.2 R18.2
NetR20_1: R20.1 U2.9 | length 3.6
  Top Layer w0.2: U2.9 33.65,21.25 34.4,20.5 R20.1
NetR20_2: R20.2 R21.1 | length 1
  Top Layer w0.2: R20.2 R21.1
NetR25_2: R25.2 U1.47 | length 15.9
  Top Layer w0.2: v1(7.5,14.7) 7.5,14.643 8.25,13.893 R25.2 ; U1.47 14.5,21.877 14.6,21.977 v1(14.6,22.058)
  Bottom Layer w0.2: v1(7.5,14.7) 7.5,15.4 8,15.9 8.7,15.9 10.175,17.375 10.175,20.595 11.638,22.058 v1(14.6,22.058)
NetR31_2: R31.2 SW2.1 | length 36.3
  Top Layer w0.2: v1(10.2,31.4) R31.2 ; SW2.1 v1(27.975,8.5)
  Bottom Layer w0.2: v1(10.2,31.4) 10.2,29.25 12.925,26.525 20.15,26.525 21.8,24.875 21.8,15.5 27.94,9.36 27.94,8.535 v1(27.975,8.5)
NetR32_1: R32.1 SW1.1 | length 2.3
  Top Layer w0.2: R32.1 11.2,2.55 SW1.1
NetR33_2: R33.2 U1.46 | length 16.7
  Top Layer w0.2: v1(8.15,14.7) 8.15,14.643 8.8,13.993 8.8,12.363 8.683,12.246 R33.2 ; U1.46 14.9,21.364 15,21.464 v1(15,21.545)
  Bottom Layer w0.2: v1(8.15,14.7) 8.15,14.781 7.945,14.986 7.945,15.35 8.145,15.55 8.845,15.55 10.525,17.23 10.525,20.45 11.783,21.708 14.243,21.708 14.405,21.545 v1(15,21.545)
PREV_BANK: J3.1 U1.16 | length 26.3
  Top Layer w0.2: v1(11.1,12.2) 11.3,12.4 U1.16 ; v1(24.3,5.08) J3.1
  Bottom Layer w0.2: v1(11.1,12.2) 9.4,10.5 9.4,7.6 10.5,6.5 19.3,6.5 20.5,5.3 24.08,5.3 v1(24.3,5.08)
QSPI1_SCLK: U1.52 U4.6 | length 19.3
  Top Layer w0.2: U1.52 12.5,21.405 10.8,23.105 10.8,25.7 11.4,26.3 20.1,26.3 21,27.2 21,28.6 20.735,28.865 U4.6
QSPI1_SD0: U1.53 U4.5 | length 16.8
  Top Layer w0.2: U1.53 12.1,21.3 10.4,23 10.4,25.9 11.2,26.7 19.7,26.7 20,27 U4.5
QSPI1_SD1: U1.55 U4.2 | length 13.2
  Top Layer w0.2: U1.55 11.3,21.1 9.6,22.8 9.6,27.4 12.335,30.135 U4.2
QSPI1_SD2: U1.54 U4.3 | length 12.2
  Top Layer w0.2: U1.54 11.7,21.2 10,22.9 10,27.2 11.665,28.865 U4.3
QSPI1_SD3: U1.51 U4.7 | length 20.9
  Top Layer w0.2: U1.51 12.9,21.5 11.2,23.2 11.2,25.5 11.6,25.9 20.3,25.9 21.4,27 21.4,29.7 20.965,30.135 U4.7
RSTn: R4.2 U1.31 | length 17.4
  Top Layer w0.2: U1.31 18.6,15.2 23.1,10.7 30.5,10.7 31,11.2 R4.2
RUN: J2.1 R32.2 U1.26 | length 48.6
  Top Layer w0.2: J2.1 1.025,26.145 1.025,12.424 1.488,11.961 2.099,11.35 8.45,11.35 9.2,10.6 9.2,7.275 10.675,5.8 R32.2 16.625,5.8 19.35,8.525 v1(19.35,11.05) ; U1.26 15.3,12.98 16.03,12.25 18.775,12.25 18.775,12.4 v1(18.8,12.425)
  Bottom Layer w0.2: v1(18.8,12.425) 19.35,11.875 v1(19.35,11.05)
RX_N: P1.6 R9.1 R14.2 U3.4 | length 18.1
  Top Layer w0.2: R9.1 36.8,17.8 37.4,17.8 38.3,18.7 39.4,18.7 39.6,18.5 39.6,18.2 39.4,18 v1(38.912,18) 38.912,17.604 38.758,17.45 U3.4 ; R14.2 v1(44.3,21.15) 44.615,20.835 46.7,20.835 46.905,21.04 P1.6
  Bottom Layer w0.2: v1(38.912,18) 39.4,18 39.6,18.2 39.6,20.266 40.184,20.85 44,20.85 v1(44.3,21.15)
RX_P: P1.4 R11.1 R15.2 U3.3 | length 18
  Top Layer w0.2: R11.1 36.8,18.2 37.234,18.2 38.134,19.1 39.566,19.1 40,18.666 40,18.2 40.2,18 v1(40.687,18) 40.687,17.604 40.841,17.45 U3.3 ; R15.2 v1(44.3,20.15) 44.585,20.435 46.7,20.435 46.905,20.23 P1.4
  Bottom Layer w0.2: v1(40.687,18) 40.2,18 40,18.2 40,20.1 40.35,20.45 44,20.45 v1(44.3,20.15)
SPI0_CSn: R17.2 U1.28 | length 13.6
  Top Layer w0.2: U1.28 16.1,13.17 16.32,12.95 17.833,12.95 18.083,13.2 v1(18.1,13.2) ; v1(19.7,22) R17.2
  Bottom Layer w0.2: v1(18.1,13.2) 17.2,14.1 17.2,15.7 18.4,16.9 18.4,20.7 v1(19.7,22)
SPI0_RX: R8.2 U1.27 | length 10.5
  Top Layer w0.2: U1.27 15.7,13.075 16.175,12.6 18.25,12.6 v1(18.825,13.175) ; v1(19.7,18) R8.2
  Bottom Layer w0.2: v1(18.825,13.175) 18.825,13.203 19.2,13.578 19.2,15.4 20.3,16.5 20.3,17.4 v1(19.7,18)
SPI0_SCK: R16.2 U1.29 | length 11
  Top Layer w0.2: U1.29 17.4,14.4 17.6,14.2 v1(18.6,14.2) ; v1(19.7,21) R16.2
  Bottom Layer w0.2: v1(18.6,14.2) 17.9,14.2 17.893,14.2 17.6,14.493 17.6,14.5 17.6,15.5 18.8,16.7 18.8,20.1 v1(19.7,21)
SPI0_TX: R10.2 U1.30 | length 7
  Top Layer w0.2: U1.30 17.5,14.8 17.6,14.7 v1(18.1,14.7) ; v1(19.7,19) R10.2
  Bottom Layer w0.2: v1(18.1,14.7) 18.1,15.4 19.2,16.5 19.2,18.5 v1(19.7,19)
SWCLK: J1.4 U1.24 | length 30.1
  Top Layer w0.2: U1.24 14.5,12.79 15.74,11.55 21.05,11.55 22.7,9.9 35.1,9.9 35.56,9.44 J1.4
SWDIO: J1.5 U1.25 | length 32.4
  Top Layer w0.2: U1.25 14.9,12.885 15.885,11.9 21.3,11.9 22.9,10.3 37.6,10.3 38.1,9.8 J1.5
TCP_STATUS: R27.2 U1.14 | length 24.4
  Top Layer w0.2: v1(9.3,14.25) 9.381,14.25 9.531,14.4 U1.14 ; R27.2 v1(23.3,4.5)
  Bottom Layer w0.2: v1(9.3,14.25) 9.3,13.531 9.825,13.006 9.825,11.63 9.05,10.855 9.05,7.455 10.355,6.15 19.155,6.15 20.805,4.5 v1(23.3,4.5)
TX_N: P1.3 R6.1 R12.2 U3.6 | length 24.6
  Top Layer w0.2: R6.1 v1(37.3,14.5) ; U3.6 38.758,15.55 38.912,15.396 v1(38.912,15) ; R12.2 v1(44.3,16) 44.6,15.7 47.6,15.7 47.9,16 47.9,16.566 48.359,17.025 49.2,17.025 49.445,17.27 P1.3
  Bottom Layer w0.2: v1(37.3,14.5) 37.6,14.8 37.966,14.8 38.866,15.7 39.4,15.7 39.6,15.5 39.6,15.2 39.4,15 v1(38.912,15) 39.6,14.312 39.6,13.734 40.334,13 44.866,13 45.4,13.534 45.4,15.266 44.966,15.7 44.6,15.7 v1(44.3,16)
TX_P: P1.1 R7.1 R13.2 U3.1 | length 23.2
  Top Layer w0.2: R7.1 v1(37.3,15.5) ; v1(40.687,15) 40.687,15.396 40.841,15.55 U3.1 ; R13.2 v1(44.3,15) 44.6,15.3 47.766,15.3 48.3,15.834 48.3,16.4 48.525,16.625 49.2,16.625 49.445,16.38 P1.1
  Bottom Layer w0.2: v1(37.3,15.5) 37.6,15.2 37.8,15.2 38.7,16.1 39.566,16.1 40,15.666 40,15.2 40.2,15 v1(40.687,15) 40,14.312 40,13.9 40.5,13.4 44.7,13.4 45,13.7 45,15.1 44.8,15.3 44.6,15.3 v1(44.3,15)
UART0_RX: J1.3 U1.3 | length 52.4
  Top Layer w0.2: v1(9.304,18.504) 9.6,18.8 U1.3
  Bottom Layer w0.2: v1(9.304,18.504) 9.3,18.507 9.3,20.502 8.35,21.452 8.35,21.95 12.225,25.825 19.86,25.825 21,24.685 21,15.1 26.1,10 26.1,1.7 26.8,1 31.48,1 J1.3
UART0_TX: J1.2 U1.2 | length 50.1
  Top Layer w0.2: v1(8.8,19) 9,19.2 U1.2
  Bottom Layer w0.2: v1(8.8,19) 8.8,20.507 8,21.307 8,22.1 12.075,26.175 20.005,26.175 21.4,24.78 21.4,15.3 26.5,10.2 26.5,1.9 27,1.4 29.34,1.4 J1.2
UART1_CTS: J2.5 U1.8 | length 14.6
  Top Layer w0.2: J2.5 1.475,21.515 1.475,19.175 2,18.65 2.75,18.65 3.525,17.875 3.525,17.125 4.225,16.425 6,16.425 6.975,17.4 8.7,17.4 9.3,16.8 U1.8
UART1_RTS: J2.9 U1.9 | length 8.8
  Top Layer w0.2: J2.9 3.885,16.075 6.15,16.075 7.075,17 8.6,17 9.2,16.4 U1.9
UART1_RX: J2.3 U1.7 | length 13.2
  Top Layer w0.2: v1(7.1,18) 7.3,17.8 8.8,17.8 9.4,17.2 U1.7
  Bottom Layer w0.2: J2.3 3.88,23.7 5.475,23.7 6.675,22.5 6.675,19.525 7.1,19.1 v1(7.1,18)
UART1_TX: J2.7 U1.6 | length 8.6
  Top Layer w0.2: J2.7 3.925,18.575 8.525,18.575 9.5,17.6 U1.6
USB_DM: J2.14 R33.1 | length 2.3
  Top Layer w0.2: J2.14 5.107,12.313 7.183,12.313 R33.1
USB_DP: J2.13 R25.1 | length 5.2
  Top Layer w0.2: J2.13 2.54,12.42 3.62,12.42 4.592,13.392 5.789,13.392 5.931,13.25 R25.1
XIN: C29.1 U1.20 Y2.1 | length 7.8
  Top Layer w0.2: C29.1 11.6,8.5 Y2.1 12.65,8.25 12.9,8.5 U1.20
XOUT: R24.2 U1.21 | length 2.6
  Top Layer w0.2: U1.21 13.3,11.1 R24.2
pads on no net: Designator4.1 Designator6.1 Designator10.1 P1. P1.7 P1.8 U1.4 U1.5 U1.11 U1.12 U1.17 U1.18 U1.34 U1.35 U1.36 U1.37 U1.38 U1.39 U2.0 U2.18 U2.19 U2.21 U2.34 U2.35 U2.37 U2.38 U2.39 U2.40 U2.41 U2.42 U2.43 U2.44
copper on no net:
  other v2: 4,1.4 58,1.4 2.162,2.162 5.838,2.162 56.162,2.162 59.838,2.162 1.4,4 6.6,4 55.4,4 60.6,4 2.162,5.838 5.838,5.838 56.162,5.838 59.838,5.838 4,6.6 58,6.6 4,33.4 2.162,34.162 5.838,34.162 1.4,36 6.6,36 2.162,37.838 5.838,37.838 4,38.6

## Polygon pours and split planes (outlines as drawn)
GND on Top Layer "NONET_L02_P-001" (solid, remove dead copper, pour order 26): 45,9.5 45.5,9 52.5,9 53,8.5 53,1 52.5,0.5 9.5,0.5 9,1 9,8.5 8.5,9 1,9 0.5,9.5 0.5,30.5 1,31 8.5,31 9,31.5 9,39 9.5,39.5 49,39.5 49.5,39 49.5,29.5 49,29 45.5,29 45,28.5
CHGND on Top Layer "NONET_L02_P-001" (solid, remove dead copper, pour order 21): 51.5,11.5 52,11 53.5,11 54,11.5 54,28.5 54.5,29 61,29 61.5,29.5 61.5,39 61,39.5 52,39.5 51.5,39
GND on Top Layer "Top Layer-GND" (solid, remove dead copper, pour order 18): 42.545,28.956 42.545,26.797 42.291,26.543 42.037,26.543 33.909,26.543 33.655,26.797 33.655,27.178 33.655,28.956
GND on Bottom Layer "NONET_L02_P-001" (solid, remove dead copper, pour order 27): 45,9.5 45.5,9 52.5,9 53,8.5 53,1 52.5,0.5 9.5,0.5 9,1 9,8.5 8.5,9 1,9 0.5,9.5 0.5,30.5 1,31 8.5,31 9,31.5 9,39 9.5,39.5 49,39.5 49.5,39 49.5,29.5 49,29 45.5,29 45,28.5
CHGND on Bottom Layer "NONET_L02_P-001" (solid, remove dead copper, pour order 22): 51.5,11.5 52,11 53.5,11 54,11.5 54,28.5 54.5,29 61,29 61.5,29.5 61.5,39 61,39.5 52,39.5 51.5,39
3V3 on Internal Plane 2 (split plane): 49.4,29 45,29 45,27.752 25.5,27.752 25.435,27.744 25.374,27.718 25.322,27.678 25.282,27.626 25.256,27.565 25.248,27.5 25.248,25.252 21,25.252 20.935,25.244 20.874,25.218 20.822,25.178 20.782,25.126 20.756,25.065 20.748,25 20.748,18.5 20.756,18.435 20.782,18.374 20.822,18.322 20.874,18.282 20.935,18.256 21,18.248 23.748,18.248 23.748,12.5 23.756,12.435 23.782,12.374 23.822,12.322 23.874,12.282 23.935,12.256 24,12.248 45,12.248 45,9 53.086,9 53.086,0.51 8.89,0.51 8.89,8.89 0.51,8.89 0.51,31.11 8.89,31.11 8.89,39.49 49.4,39.49
3V3A on Internal Plane 2 (split plane): 45,12.752 29.252,12.752 29.252,27.248 45,27.248
1V2D on Internal Plane 2 (split plane): 28.748,12.752 24.252,12.752 24.252,18.5 24.244,18.565 24.218,18.626 24.178,18.678 24.126,18.718 24.065,18.744 24,18.752 21.252,18.752 21.252,24.748 25.5,24.748 25.565,24.756 25.626,24.782 25.678,24.822 25.718,24.874 25.744,24.935 25.752,25 25.752,27.248 28.748,27.248
GND on Internal Plane 1 (split plane): 49.4,29 45,29 45,9 53.086,9 53.086,0.51 8.89,0.51 8.89,8.89 0.51,8.89 0.51,31.11 8.89,31.11 8.89,39.49 49.4,39.49

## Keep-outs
Keep-Out Layer:
  the board outline again, w0.127
  text ".Layer_Name" at 9.398,44.45 h1.52

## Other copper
Top Layer:
  pour cut-out: -0.8,4 ccw(c4,4) 4,-0.8 ccw(c4,4) 8.8,4 ccw(c4,4) 4,8.8 ccw(c4,4)
  pour cut-out: -0.8,4 ccw(c4,4) 4,-0.8 ccw(c4,4) 8.8,4 ccw(c4,4) 4,8.8 ccw(c4,4)
  pour cut-out: -0.8,36 ccw(c4,36) 4,31.2 ccw(c4,36) 8.8,36 ccw(c4,36) 4,40.8 ccw(c4,36)
  pour cut-out: 53.2,4 ccw(c58,4) 58,-0.8 ccw(c58,4) 62.8,4 ccw(c58,4) 58,8.8 ccw(c58,4)
  text ".Layer_Name" at 9.398,44.45 h1.52
Bottom Layer:
  pour cut-out: -0.8,36 ccw(c4,36) 4,31.2 ccw(c4,36) 8.8,36 ccw(c4,36) 4,40.8 ccw(c4,36)
  pour cut-out: -0.8,4 ccw(c4,4) 4,-0.8 ccw(c4,4) 8.8,4 ccw(c4,4) 4,8.8 ccw(c4,4)
  pour cut-out: 53.2,4 ccw(c58,4) 58,-0.8 ccw(c58,4) 62.8,4 ccw(c58,4) 58,8.8 ccw(c58,4)
  text ".Layer_Name" at 9.398,44.45 h1.52
Internal Plane 1 (plane layer: these items are gaps in the copper):
  region: 0,40 0,31.11 8.89,31.11 8.89,40
  rectangle: 0,0 8.89,8.89
  rectangle: 53.086,0 61.976,9.017
  region: 61.8,40.005 49.4,40.005 49.4,29 45,29 45,9 62,9 62,40.005
  text ".Layer_Name" at 9.398,44.45 h1.52
Internal Plane 2 (plane layer: these items are gaps in the copper):
  rectangle: 53.086,0 61.976,9.017
  region: 0,40 0,31.11 8.89,31.11 8.89,40
  rectangle: 0,0 8.89,8.89
  rectangle: 10.9,7.4 14.9,10.6
  rectangle: 36.9,22.5 40.1,26.5
  region: 61.8,40.005 49.4,40.005 49.4,29 45,29 45,9 62,9 62,40.005
  lines w0.5: 62,12.5 29,12.5 ; 62,27.5 29,27.5 ; 29,12.5 24,12.5 24,18.5 21,18.5 21,25 25.5,25 25.5,27.5 29,27.5 ; 29,12.5 29,27.5
  text ".Layer_Name" at 9.398,44.45 h1.52

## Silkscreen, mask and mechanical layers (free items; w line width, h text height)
Top Overlay:
  rectangle: 7.62,33.02 33.62,40.02
  text ".Layer_Name" at 9.398,44.482 h1.52
  text "WIZ505SR-RP V100" at 35.3,37.8 h2
  text "BOOT" at 27.9,10.25 h1.5
  text "RESET" at 11.8,4.25 h1.5
Bottom Overlay:
  lines w0.2: 11.35,2 24.4,2 ; 11.35,4 24.35,4 ; 11.35,5.9 24.35,5.9
  text ".Layer_Name" at 9.398,44.45 h1.52
  text "3V3" at 8.041,27.218 h0.8
  text "RST" at 0.475,26.646 h0.8 r270
  text "3V3" at 8.004,24.575 h0.8
  text "RX" at 0.475,24.502 h0.8 r270
  text "FAC_RST" at 10.849,22.142 h0.8
  text "CTS" at 0.475,21.546 h0.8 r270
  text "IO9" at 7.454,19.575 h0.8
  text "TX" at 0.475,19.544 h0.8 r270
  text "BOOT" at 8.744,17 h0.8
  text "RTS" at 0.475,16.488 h0.8 r270
  text "GND" at 8.146,14.475 h0.8
  text "GND" at 0.475,13.904 h0.8 r270
  text "DM" at 7.461,11.95 h0.8
  text "DP" at 0.5,11.802 h0.8 r270
  text "WIZ505SR-RP" at 24.35,6.15 h2
  text "http://wiznet.io" at 24.25,4.5 h1.5
  text "Designed by WIZnet" at 24.35,2.5 h1.5
Top Paste:
  text ".Layer_Name" at 9.398,44.45 h1.52
Bottom Paste:
  text ".Layer_Name" at 9.398,44.45 h1.52
Top Solder:
  text ".Layer_Name" at 9.398,44.45 h1.52
Bottom Solder:
  text ".Layer_Name" at 9.398,44.45 h1.52
Drill Guide:
  text ".Layer_Name" at 9.398,44.45 h1.52
Mechanical 2:
  lines w0.127: 69.291,16.129 95.453,16.129 ; 69.291,18.923 95.453,18.923 ; 0,1.27 ccw(c1.27,1.27) 1.27,0 60.73,0 ccw(c60.73,1.27) 62,1.27 62,38.73 ccw(c60.73,38.73) 60.73,40 1.27,40 ccw(c1.27,38.73) 0,38.73 0,1.27 ; 67.945,4.775 ccw(c68.656,4.775) 68.656,4.064 95.834,4.064 ccw(c95.834,4.775) 96.545,4.775 96.545,24.003 ccw(c95.834,24.003) 95.834,24.714 68.656,24.714 ccw(c68.656,24.003) 67.945,24.003 67.945,4.775
  text "BOARD NAME : WIZ505SR-RP" at 0,55.626 h1.52
  text "VERSION : V100" at 0,52.832 h1.52
  text "SIZE : 62mmX40mmX1.6T" at 0,50.038 h1.52
  text "GERBER DATE : 2022.05.04" at 0,47.244 h1.52
  text "LAYER :" at 0,44.45 h1.52
  text "Layer Stack Up Detail for:" at 69.418,22.606 h1.02
  text "WIZ505SR-RP_V100.PcbDoc" at 69.291,20.193 h1.27
  text "Layer Name : 4L  1.6T" at 69.418,17.018 h1.02
  text "Top Layer" at 69.291,13.335 h1.52
  text "Internal Plane 1 (GND)" at 69.291,10.541 h1.52
  text "Internal Plane 2 (POWER)" at 69.291,7.874 h1.52
  text "Bottom Layer" at 69.291,5.334 h1.52
  text "KS Technology artwork" at 67.945,0 h5.08
Drill Drawing:
  text ".Layer_Name" at 9.398,44.45 h1.52
  text ".Legend" at 69.977,27.432 h1.02

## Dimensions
1.27,0 to 1.27,40 on Mechanical 2
0,1.27 to 62,1.27 on Mechanical 2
